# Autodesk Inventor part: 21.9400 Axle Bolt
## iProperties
Created: 2010-11
Part Number: 21.9400 Axle Bolt
Document SubType Name: Modeling
Designer: Administrator
Density: 7.85 g/cm^3
Material: Steel
Mass: 34.4608 g
Surface Area: 26.0406 cm^2
Volume: 4.38991 cm^3
Author: Administrator
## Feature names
1. Base1
